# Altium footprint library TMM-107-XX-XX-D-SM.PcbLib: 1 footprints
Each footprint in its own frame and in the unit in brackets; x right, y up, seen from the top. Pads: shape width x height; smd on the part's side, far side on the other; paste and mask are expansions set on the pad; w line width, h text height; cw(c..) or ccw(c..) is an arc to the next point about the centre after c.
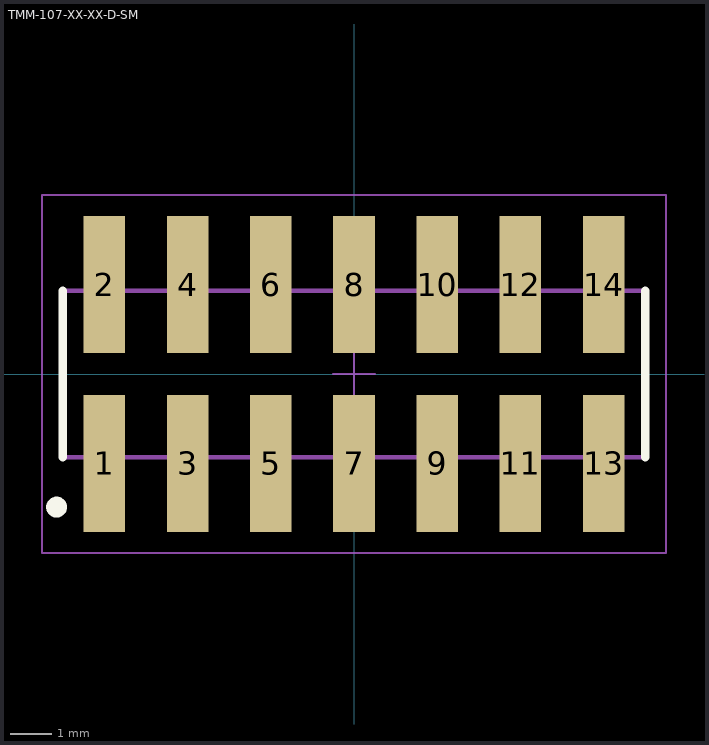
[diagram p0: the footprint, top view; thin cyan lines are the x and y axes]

## TMM-107-XX-XX-D-SM [mm] "2.00mm pitch, 14 pin, terminal strip; double row, SMT"
height 2.77
pads (14):
  rect 1x3.3 smd mask+0: 1(-6,-2.15) 2(-6,2.15) 3(-4,-2.15) 4(-4,2.15) 5(-2,-2.15) 6(-2,2.15) 7(0,-2.15) 8(0,2.15) 9(2,-2.15) 10(2,2.15) 11(4,-2.15) 12(4,2.15) 13(6,-2.15) 14(6,2.15)
Top Overlay:
  circle w0.25: c-7.15,-3.2 r0.125
  lines w0.2: -7,-2 -7,2 ; 7,-2 7,2
Mechanical 12:
  lines w0.001: -7,-2 7,-2 7,2 -7,2 -7,-2
Mechanical 13:
  lines w0.1: -7,-2 7,-2 7,2 -7,2 -7,-2
  text ".Designator" at 0,-0.127 h1.52
Mechanical 15:
  lines w0.05: -0.5,0 0.5,0 ; 0,-0.5 0,0.5 ; -7.5,-4.3 7.5,-4.3 7.5,4.3 -7.5,4.3 -7.5,-4.3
